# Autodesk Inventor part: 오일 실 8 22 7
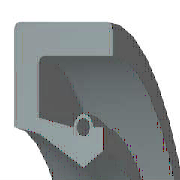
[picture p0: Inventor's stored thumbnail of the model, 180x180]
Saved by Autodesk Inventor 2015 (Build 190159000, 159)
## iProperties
IsCustomPart: 1
Created: 2012-02
Part Number: 오일 실 8 22 7
Material: 고무
Description: 오일-실
Document SubType Name: Modeling
Standard: KS B 2804
Designer: test
Standards Organization: KS
Language: ko-KR
Size Designation: S - 8 22 7
Categories: <MemberInstance><Categories><Category DisplayName="샤프트 부품" InternalName="7f7aeb1f-a693-4053-b835-cee3144e0d98" Mnemonic="SHFT"><Category DisplayName="실링" Intern
Density: 0.93 g/cm^3
Appearance: 고무 - 검은색 - 버전 1.1
Author: test
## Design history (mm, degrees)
revolve "본체" stored, may be unused: angle "d17" = 90 deg
revolve "스프링1" stored, may be unused: angle "d18" = 90 deg
body "Solid1"
sketch "스케치1"
  geometry: L1 (0, 11)-(7, 11); L2 (7, 11)-(7, 9.75); L3 (7, 9.75)-(1.75, 9.75); L4 (0, 11)-(0, 6.1); L5 (0, 6.1)-(1.75, 5.75); L6 (1.75, 5.75)-(4.9, 4); L7 (4.9, 4)-(0, 4); L8 (6.3, 4.875)-(6.3, 6.1); L9 (0, 0)-(9.586, 0) reference; L10 (4.9, 4)-(6.3, 4.875); L11 (0, 18)-(0, -3) reference; L12 (-1.917, 0)-(11.503, 0) reference; L13 (4.2, 6.1)-(1.75, 6.59); L14 (1.75, 6.59)-(1.75, 9.75); L15 (6.3, 6.1)-(5.6, 6.1); C1 r 0.455 at (4.9, 6.1); A1 r 0.7 centre (4.9, 6.1) between (5.6, 6.1) and (4.2, 6.1)
  constraints: 26 end point, 5 horizontal alignment, 4 perpendicular, 2 centre point, 2 collinear, 2 horizontal, 2 parallel, 2 point on circle, 2 point on line, 2 vertical alignment, 1 coincident
  dimensions: "d0" = 22 diameter of L1 L9 (= SD2); "d1" = 9.75 diameter of L8.start L9 (= ABDM); "d2" = 1.25 distance of L1.end L2.end (computed from SD); "d3" = 0.91 diameter of C1 (= SPDI); "d4" = 1.4 diameter of A1 (= SPDA); "d5" = 8 diameter of L6.end L9 (= NND); "d6" = 11.5 diameter of L5.end L9 (= TKDM); "d7" = 12.2 diameter of L4.end L9 (= HLDM); "d8" = 4.9 distance from line of C1.centre L4 (= SPDST); "d9" = 6.3 distance between parallel lines of L8 L4 (= SDI); "d10" = 7 distance between parallel lines of L2 L4 (= SWDT); "d12" = 1.75 distance between parallel lines of L14 L4 (= SD)
fillet "모깎기1" dims "d11" = 0.3 (= RR)
other parameters: "SD2" = 22 [user parameter; used in 1 equation term], "SWDT" = 7 [user parameter; used in 1 equation term], "RR" = 0.3 [user parameter; used in 1 equation term], "SD" = 1.75 [user parameter; used in 2 equation terms], "NND" = 8 [user parameter; used in 1 equation term], "SPDA" = 1.4 [user parameter; used in 1 equation term], "SPDI" = 0.91 [user parameter; used in 1 equation term], "TKDM" = 11.5 [user parameter; used in 1 equation term], "HLDM" = 12.2 [user parameter; used in 1 equation term], "ABDM" = 9.75 [user parameter; used in 1 equation term], "SDI" = 6.3 [user parameter; used in 1 equation term], "SPDST" = 4.9 [user parameter; used in 1 equation term], "d13" = 0, "d14" = 0, "d15" = 0, "LAB" = 0.35 [user parameter]
